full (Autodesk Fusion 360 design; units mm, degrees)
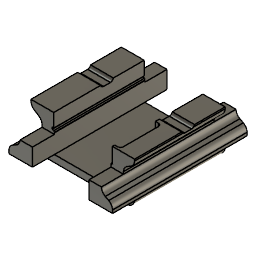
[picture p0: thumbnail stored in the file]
base_feature "Base Feature2"
base_feature "Base Feature1"
offset_faces "OffsetFaces1" distance 0.5
combine "Combine1"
